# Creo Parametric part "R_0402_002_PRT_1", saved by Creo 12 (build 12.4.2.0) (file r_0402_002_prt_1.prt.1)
Units: Custom; MM, KILOGRAM, SECS

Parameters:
  PTC_WM_ITERATION = "0"
  PTC_WM_VERSION = "-.0"
  PTC_WM_LIFECYCLE_STATE = "In Work"
  PTC_WM_LIFECYCLE = "MO_CADDocument"
  PTC_WM_CREATED_BY = "Maximilian Roepper (Z0017RMS: MO)"
  PTC_WM_CREATED_ON = "18-Sep-26 11:36:42 AM"
  PTC_WM_MODIFIED_BY = "Maximilian Roepper (Z0017RMS: MO)"
  PTC_WM_MODIFIED_ON = "18-Sep-26 11:36:46 AM"
  PDMLINKNUMBER = "PDM000071455142"
  PTC_WM_NAME = "r_0402_002_prt_1.prt"
  PTC_WM_NUMBER = "PDM000071455142"

Other parameters: WEIGHT, WEIGHT_FACTOR, WEIGHT_ADD, _MASS_TEMP, _DIFF_TEMP, MC_ERRORS, SUPPLIER

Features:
  1. coordinate system
  2. datum plane "PRT_YZ"
  3. datum plane "PRT_XY"
  4. datum plane "PRT_XZ"
  5. coordinate system
  6. datum axis
  7. datum axis
  8. datum axis
  9. coordinate system
  10. imported feature
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
Other named items: PRT, SIEMENS_MO, DRW_VIEW_ORG, PRT_X, PRT_Y, PRT_Z, CS0, ROUGH_GROB

Layers: 00_STD_CSYS-KSYS, 01_STD_PLANES-EBENEN, 02_STD_AXES-ACHSEN, 03_STD_CSYS-KSYS, 24_IMPORT_FEAT-IMPORT_KE

Surfaces: 18 plane, 8 cylinder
